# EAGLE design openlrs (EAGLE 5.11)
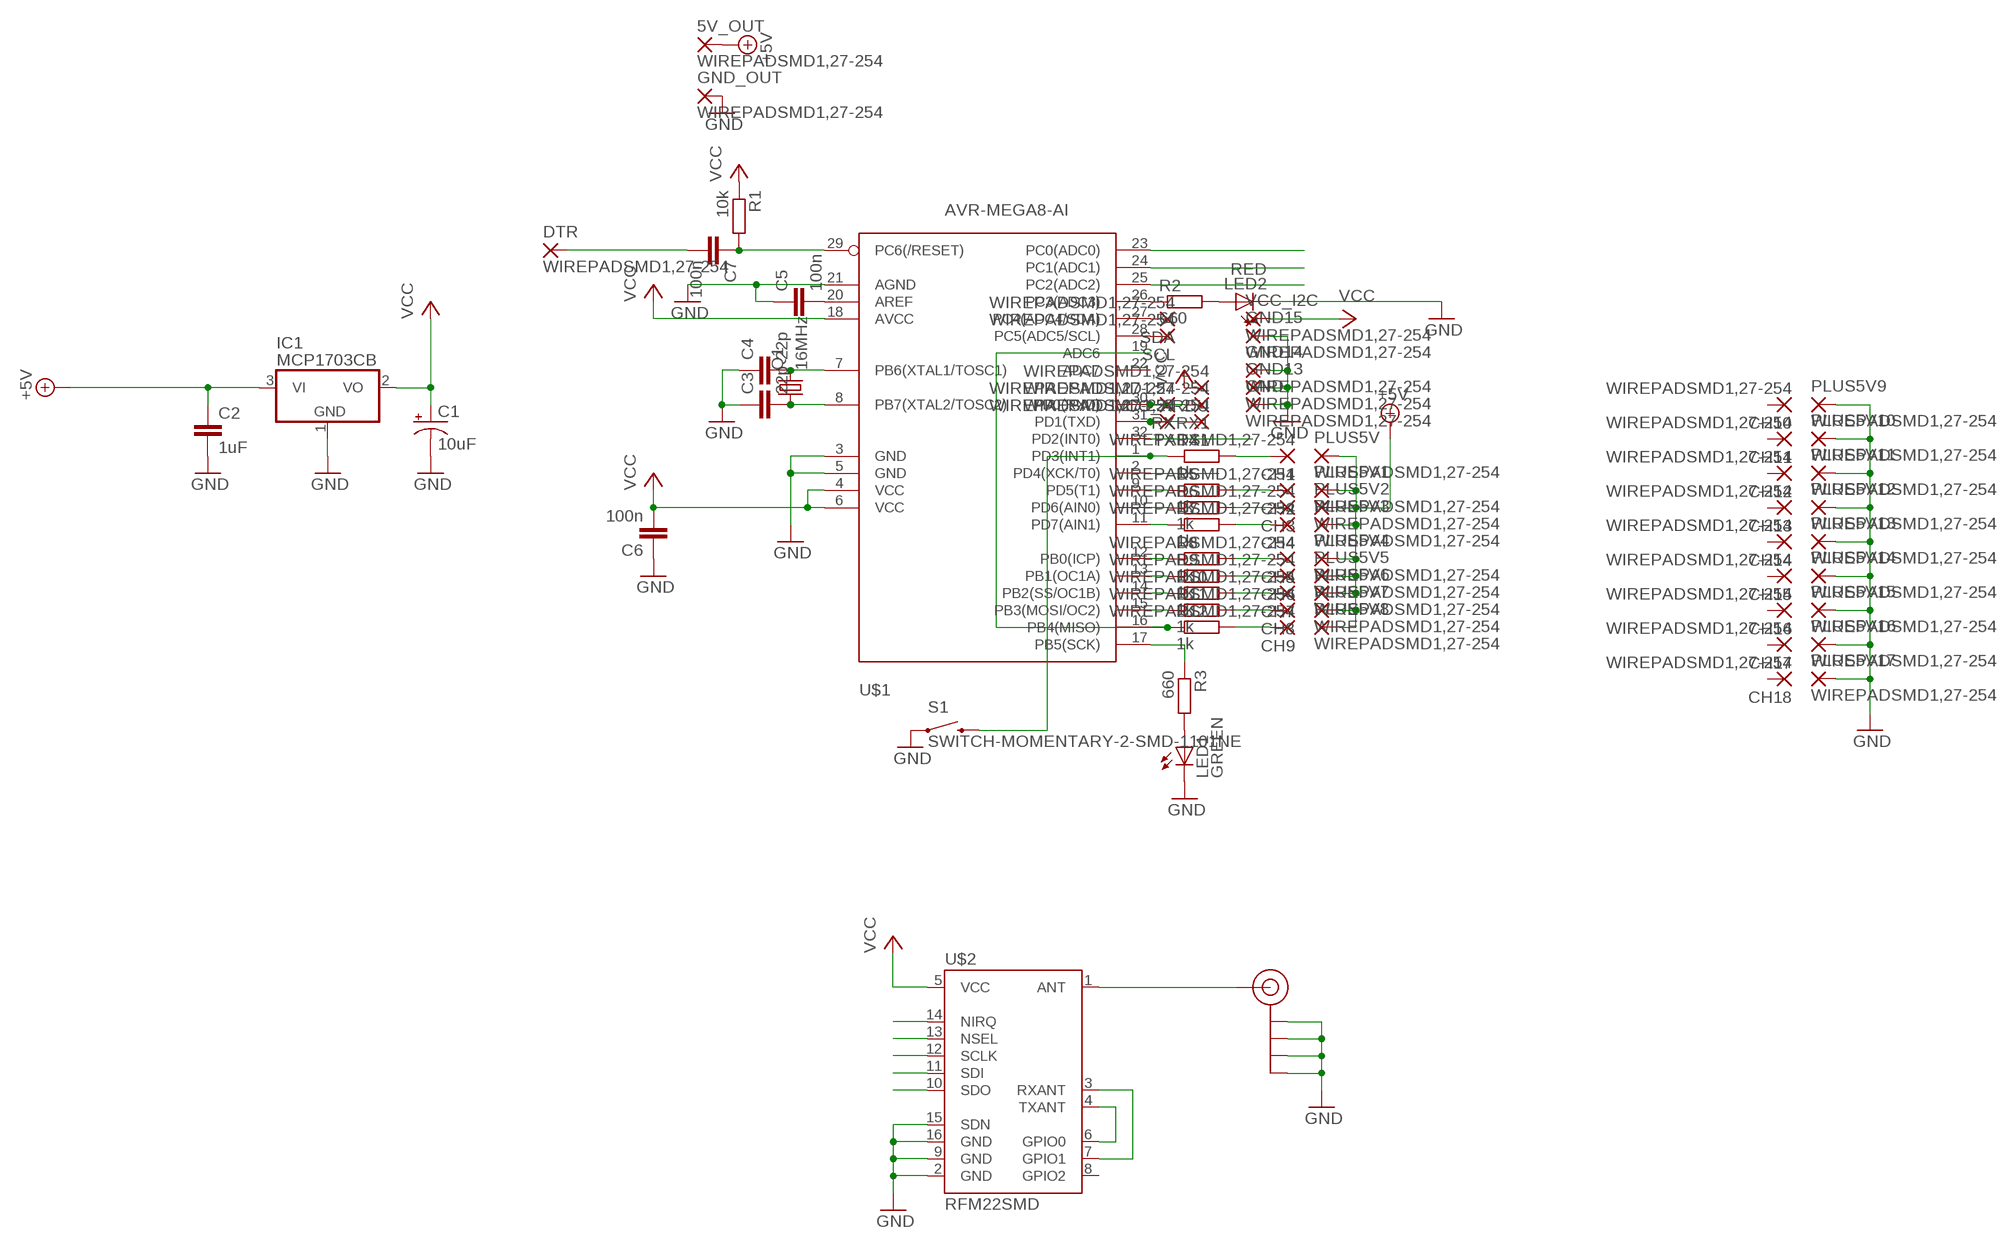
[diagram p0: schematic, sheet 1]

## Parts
5V_OUT  WIREPADSMD1,27-254  [SMD1,27-2,54]
C1  10uF  CAP_POL3528  [EIA3528]
C2  1uF  C-EUC0805K  [C0805K]
C3  22p  C-EUC0603K  [C0603K]
C4  22p  C-EUC0603K  [C0603K]
C5  100n  C-EUC0603K  [C0603K]
C6  100n  C-EUC0603K  [C0603K]
C7  100n  C-EUC0603K  [C0603K]
CH1  WIREPADSMD1,27-254  [SMD1,27-2,54]
CH2  WIREPADSMD1,27-254  [SMD1,27-2,54]
CH3  WIREPADSMD1,27-254  [SMD1,27-2,54]
CH4  WIREPADSMD1,27-254  [SMD1,27-2,54]
CH5  WIREPADSMD1,27-254  [SMD1,27-2,54]
CH6  WIREPADSMD1,27-254  [SMD1,27-2,54]
CH7  WIREPADSMD1,27-254  [SMD1,27-2,54]
CH8  WIREPADSMD1,27-254  [SMD1,27-2,54]
CH9  WIREPADSMD1,27-254  [SMD1,27-2,54]
CH10  WIREPADSMD1,27-254  [SMD1,27-2,54]
CH11  WIREPADSMD1,27-254  [SMD1,27-2,54]
CH12  WIREPADSMD1,27-254  [SMD1,27-2,54]
CH13  WIREPADSMD1,27-254  [SMD1,27-2,54]
CH14  WIREPADSMD1,27-254  [SMD1,27-2,54]
CH15  WIREPADSMD1,27-254  [SMD1,27-2,54]
CH16  WIREPADSMD1,27-254  [SMD1,27-2,54]
CH17  WIREPADSMD1,27-254  [SMD1,27-2,54]
CH18  WIREPADSMD1,27-254  [SMD1,27-2,54]
DTR  WIREPADSMD1,27-254  [SMD1,27-2,54]
GND  WIREPADSMD1,27-254  [SMD1,27-2,54]
GND13  WIREPADSMD1,27-254  [SMD1,27-2,54]
GND14  WIREPADSMD1,27-254  [SMD1,27-2,54]
GND15  WIREPADSMD1,27-254  [SMD1,27-2,54]
GND_OUT  WIREPADSMD1,27-254  [SMD1,27-2,54]
IC1  MCP1703CB  [SOT23]
J$1  SMA_EDGE  [SMA-EDGE]
LED1  GREEN  LEDCHIPLED_0603  [CHIPLED_0603]
LED2  RED  LEDCHIPLED_0603  [CHIPLED_0603]
PLUS5V  WIREPADSMD1,27-254  [SMD1,27-2,54]
PLUS5V1  WIREPADSMD1,27-254  [SMD1,27-2,54]
PLUS5V2  WIREPADSMD1,27-254  [SMD1,27-2,54]
PLUS5V3  WIREPADSMD1,27-254  [SMD1,27-2,54]
PLUS5V4  WIREPADSMD1,27-254  [SMD1,27-2,54]
PLUS5V5  WIREPADSMD1,27-254  [SMD1,27-2,54]
PLUS5V6  WIREPADSMD1,27-254  [SMD1,27-2,54]
PLUS5V7  WIREPADSMD1,27-254  [SMD1,27-2,54]
PLUS5V8  WIREPADSMD1,27-254  [SMD1,27-2,54]
PLUS5V9  WIREPADSMD1,27-254  [SMD1,27-2,54]
PLUS5V10  WIREPADSMD1,27-254  [SMD1,27-2,54]
PLUS5V11  WIREPADSMD1,27-254  [SMD1,27-2,54]
PLUS5V12  WIREPADSMD1,27-254  [SMD1,27-2,54]
PLUS5V13  WIREPADSMD1,27-254  [SMD1,27-2,54]
PLUS5V14  WIREPADSMD1,27-254  [SMD1,27-2,54]
PLUS5V15  WIREPADSMD1,27-254  [SMD1,27-2,54]
PLUS5V16  WIREPADSMD1,27-254  [SMD1,27-2,54]
PLUS5V17  WIREPADSMD1,27-254  [SMD1,27-2,54]
Q1  16MHz  CRYSTAL5X3  [CRYSTAL-SMD-5X3]
R1  10k  R-EU_R0603  [R0603]
R2  660  R-EU_R0603  [R0603]
R3  660  R-EU_R0603  [R0603]
R4  1k  R-EU_R0603  [R0603]
R5  1k  R-EU_R0603  [R0603]
R6  1k  R-EU_R0603  [R0603]
R7  1k  R-EU_R0603  [R0603]
R8  1k  R-EU_R0603  [R0603]
R9  1k  R-EU_R0603  [R0603]
R10  1k  R-EU_R0603  [R0603]
R11  1k  R-EU_R0603  [R0603]
R12  1k  R-EU_R0603  [R0603]
RX  WIREPADSMD1,27-254  [SMD1,27-2,54]
RX1  WIREPADSMD1,27-254  [SMD1,27-2,54]
S1  SWITCH-MOMENTARY-2-SMD-1101NE  [TACTILE-SWITCH-1101NE]
SCL  WIREPADSMD1,27-254  [SMD1,27-2,54]
SDA  WIREPADSMD1,27-254  [SMD1,27-2,54]
TX  WIREPADSMD1,27-254  [SMD1,27-2,54]
TX1  WIREPADSMD1,27-254  [SMD1,27-2,54]
U$1  AVR-MEGA8-AI  [TQFP32-08]
U$2  RFM22SMD  [RFM22-XXX-S2]
VCC_ARDU  WIREPADSMD1,27-254  [SMD1,27-2,54]
VCC_I2C  WIREPADSMD1,27-254  [SMD1,27-2,54]

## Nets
+5V: 5V_OUT.1(P) C2.1 IC1.3(VI) PLUS5V1.1(P) PLUS5V2.1(P) PLUS5V3.1(P) PLUS5V4.1(P) PLUS5V5.1(P) PLUS5V6.1(P) PLUS5V7.1(P) PLUS5V8.1(P) PLUS5V.1(P)
GND: C1.C(-) C2.2 C3.1 C4.1 C5.1 C6.1 GND13.1(P) GND14.1(P) GND15.1(P) GND.1(P) GND_OUT.1(P) IC1.1(GND) J$1.GND@0(GND) J$1.GND@1(GND) J$1.GND@2(GND) J$1.GND@3(GND) LED1.C LED2.C PLUS5V9.1(P) PLUS5V10.1(P) PLUS5V11.1(P) PLUS5V12.1(P) PLUS5V13.1(P) PLUS5V14.1(P) PLUS5V15.1(P) PLUS5V16.1(P) PLUS5V17.1(P) S1.P$1 U$1.3(GND) U$1.5(GND) U$1.21(AGND) U$2.2(GND) U$2.9(GND) U$2.15(SDN) U$2.16(GND)
INT0: U$1.32(PD2(INT0)) U$2.14(NIRQ)
N$1: C7.1 R1.2 U$1.29(PC6(/RESET))
N$2: C4.2 Q1.3 U$1.7(PB6(XTAL1/TOSC1))
N$3: C3.2 Q1.1 U$1.8(PB7(XTAL2/TOSC2))
N$4: C5.2 U$1.20(AREF)
N$5: R2.1 U$1.26(PC3(ADC3))
N$6: R3.1 U$1.17(PB5(SCK))
N$7: LED1.A R3.2
N$8: LED2.A R2.2
N$9: R12.1 U$1.16(PB4(MISO)) U$1.19(ADC6)
N$10: R4.1 S1.P$2 U$1.1(PD3(INT1))
N$11: CH1.1(P) R4.2
N$12: R5.1 U$1.9(PD5(T1))
N$13: CH2.1(P) R5.2
N$14: R6.1 U$1.10(PD6(AIN0))
N$15: CH3.1(P) R6.2
N$16: R7.1 U$1.11(PD7(AIN1))
N$17: CH4.1(P) R7.2
N$18: R8.1 U$1.12(PB0(ICP))
N$19: CH5.1(P) R8.2
N$20: R9.1 U$1.13(PB1(OC1A))
N$21: CH6.1(P) R9.2
N$22: R10.1 U$1.14(PB2(SS/OC1B))
N$23: CH7.1(P) R10.2
N$24: R11.1 U$1.15(PB3(MOSI/OC2))
N$25: CH8.1(P) R11.2
N$26: CH9.1(P) R12.2
N$27: J$1.SIG(SIGNAL) U$2.1(ANT)
N$28: U$2.4(TXANT) U$2.6(GPIO0)
N$29: U$2.3(RXANT) U$2.7(GPIO1)
N$30: RX1.1(P) RX.1(P) U$1.30(PD0(RXD))
N$31: TX1.1(P) TX.1(P) U$1.31(PD1(TXD))
N$32: C7.2 DTR.1(P)
N$33: SDA.1(P) U$1.27(PC4(ADC4/SDA))
N$35: SCL.1(P) U$1.28(PC5(ADC5/SCL))
SCK: U$1.25(PC2(ADC2)) U$2.12(SCLK)
SDI: U$1.24(PC1(ADC1)) U$2.11(SDI)
SDO: U$1.23(PC0(ADC0)) U$2.10(SDO)
VCC: C1.A(+) C6.2 IC1.2(VO) R1.1 U$1.4(VCC) U$1.6(VCC) U$1.18(AVCC) U$2.5(VCC) VCC_ARDU.1(P) VCC_I2C.1(P)
XCK: U$1.2(PD4(XCK/T0)) U$2.13(NSEL)
Unconnected: CH10.1(P) CH11.1(P) CH12.1(P) CH13.1(P) CH14.1(P) CH15.1(P) CH16.1(P) CH17.1(P) CH18.1(P) U$1.22(ADC7) U$2.8(GPIO2)

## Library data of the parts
5V_OUT CH1-CH18 DTR GND GND13-GND15 GND_OUT PLUS5V PLUS5V1-PLUS5V17 RX RX1 SCL SDA TX TX1 VCC_ARDU VCC_I2C = wirepad:WIREPAD: Wire PAD connect wire on PCB
C1 = SparkFun:CAP_POL: Capacitor Polarized
C2-C7 = resistor:C-EU: CAPACITOR, European symbol
IC1 = linear:MCP1703: 250 mA, 16V, Low Quiescent Current LDO Regulator Source: http://ww1.microchip.com/downloads/en/DeviceDoc/22049b.pdf
J$1 = SparkFun:SMA_EDGE: SMA Antenna Connector End launch SMA connector. The paste layer has been removed so that the connector can be hand soldered onto the board after reflow.
LED1 LED2 = led:LED: LED
Q1 = SparkFun:CRYSTAL: Crystals
R1-R12 = resistor:R-EU_: RESISTOR, European symbol
S1 = SparkFun:SWITCH-MOMENTARY-2
U$1 = SparkFun:AVR-MEGA8: MICROCONTROLLER 8 Kbytes FLASH 1 kbytes SRAM 512 bytes EEPROM USART 6-channel 10 bit ADC 2-channel 8 bit ADC
U$2 = SparkFun:RFM22: Description: The RFM22 is a low-power, low cost radio that is capable of operating in the 434MHz and 900MHz open bands. It's frequency is software defined and there are some very good libraries written for it.

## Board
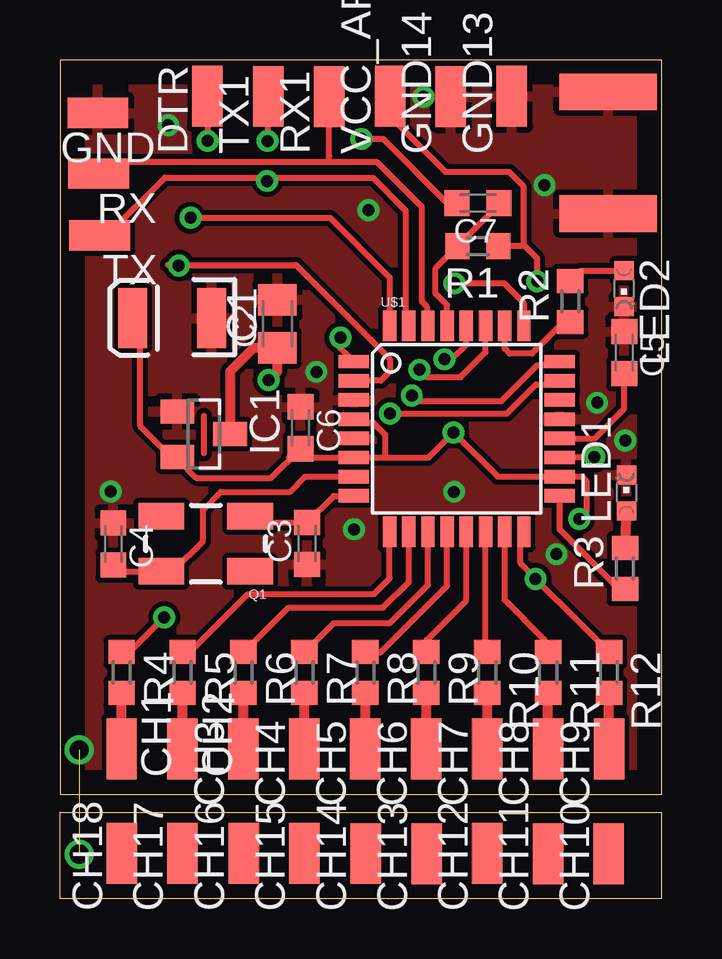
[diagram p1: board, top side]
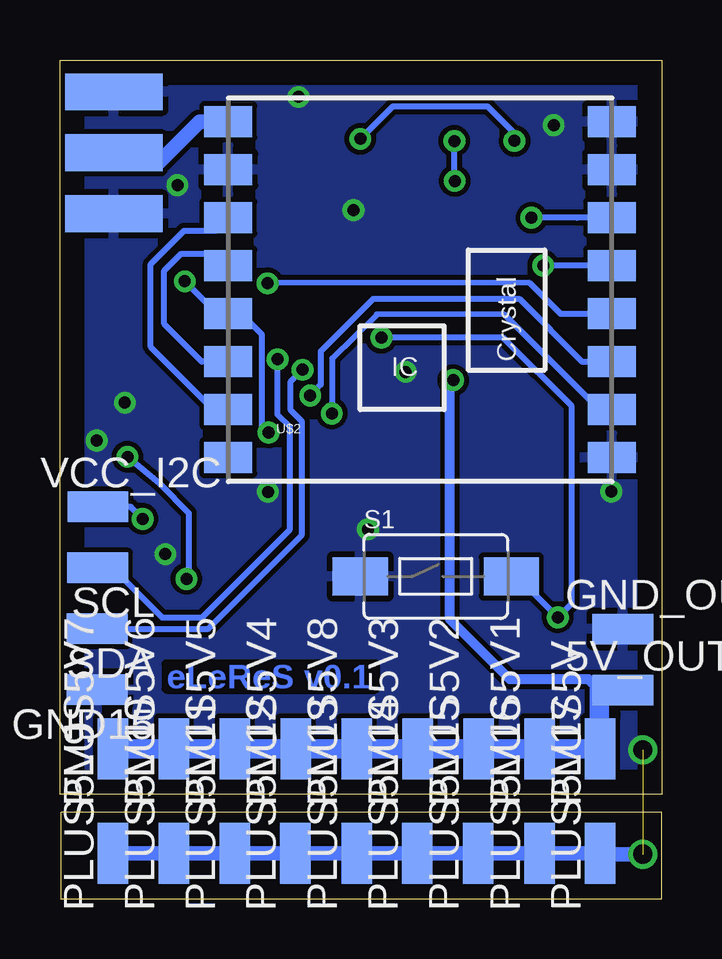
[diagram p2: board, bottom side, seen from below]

Size 25.1 x 34.96 mm. Coordinates in mm from the lower left corner, seen from the top.
Outline: 0.01,3.6 25.08,3.6 25.08,0 0.02,0 0.02,3.61
Outline: 0,4.34 25.1,4.34 25.1,34.96 0,34.96 0,4.34
Copper layers (1*16): Top 0.035mm / dielectric 1.5mm / Bottom 0.035mm
Design rules "default": minimum track width 10mil, minimum drill 24mil, track to track 8mil, track to pad 8mil, pad to pad 8mil, via to via 8mil, smd to smd 8mil, copper to edge 40mil, drill to drill 8mil, minimum pad ring 10mil, minimum via ring 8mil, stop-mask expansion 4mil, vias tented up to drill 0mil, thermal gap 10mil

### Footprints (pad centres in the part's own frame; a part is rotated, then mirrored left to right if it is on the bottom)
SMD1,27-2,54 = smd 1.27 x 2.54: 1 0,0
EIA3528 = smd 1.2 x 2.5: A 1.65,0; C -1.65,0
C0805K = smd 1.3 x 1.6: 1 -1,0; 2 1,0
C0603K = smd 1.05 x 1.08: 1 -0.875,0; 2 0.875,0
SOT23 = smd 1 x 1.4: 1 -0.95,-1.1; 2 0.95,-1.1; 3 0,1.1
SMA-EDGE = smd 1.524 x 4.064: GND@0 0,0; GND@1 5.08,0; SIG 2.54,0 | smd 1.524 x 4.064 bottom: GND@2 0,0; GND@3 5.08,0
CHIPLED_0603 = smd 0.8 x 0.8: A 0,-0.75; C 0,0.75
CRYSTAL-SMD-5X3 = smd 1.9 x 1.1: 1 -1.85,-1.15; 2 1.85,-1.15; 3 1.85,1.15; 4 -1.85,1.15
R0603 = smd 1 x 1.1: 1 -0.85,0; 2 0.85,0
TACTILE-SWITCH-1101NE = smd 2.3 x 1.6: P$1 -3.15,0; P$2 3.15,0
TQFP32-08 = smd 1.27 x 0.559: 1 -4.293,2.8; 2 -4.293,2; 3 -4.293,1.2; 4 -4.293,0.4; 5 -4.293,-0.4; 6 -4.293,-1.2; 7 -4.293,-2; 8 -4.293,-2.8; 17 4.293,-2.8; 18 4.293,-2; 19 4.293,-1.2; 20 4.293,-0.4; 21 4.293,0.4; 22 4.293,1.2; 23 4.293,2; 24 4.293,2.8 | smd 0.559 x 1.27: 9 -2.8,-4.293; 10 -2,-4.293; 11 -1.2,-4.293; 12 -0.4,-4.293; 13 0.4,-4.293; 14 1.2,-4.293; 15 2,-4.293; 16 2.8,-4.293; 25 2.8,4.293; 26 2,4.293; 27 1.2,4.293; 28 0.4,4.293; 29 -0.4,4.293; 30 -1.2,4.293; 31 -2,4.293; 32 -2.8,4.293
RFM22-XXX-S2 = smd 2 x 1.3: 1 -8,7; 2 -8,5; 3 -8,3; 4 -8,1; 5 -8,-1; 6 -8,-3; 7 -8,-5; 8 -8,-7; 9 8,-7; 10 8,-5; 11 8,-3; 12 8,-1; 13 8,1; 14 8,3; 15 8,5; 16 8,7

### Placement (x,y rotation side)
5V_OUT  1.63,8.69 270 bottom
C1  4.68,24.21 180 top
C2  9.07,23.96 90 top
C3  10.31,14.8 90 top
C4  2.23,14.79 270 top
C5  23.53,22.76 270 top
C6  10.04,19.62 270 top
C7  17.43,29 180 top
CH1  2.57,6.25 180 top
CH2  5.11,6.25 180 top
CH3  7.65,6.25 0 top
CH4  10.19,6.25 0 top
CH5  12.73,6.25 0 top
CH6  15.27,6.25 0 top
CH7  17.81,6.25 0 top
CH8  20.35,6.25 0 top
CH9  22.89,6.25 0 top
CH10  22.88,1.87 0 top
CH11  20.35,1.87 0 top
CH12  17.82,1.88 0 top
CH13  15.29,1.87 0 top
CH14  12.74,1.88 0 top
CH15  10.19,1.88 0 top
CH16  7.66,1.89 0 top
CH17  5.11,1.88 0 top
CH18  2.58,1.89 0 top
DTR  6.14,33.44 0 top
GND  1.58,32.75 90 top
GND13  18.84,33.44 0 top
GND14  16.29,33.44 0 top
GND15  23.56,8.71 90 bottom
GND_OUT  1.63,11.23 270 bottom
IC1  6,19.36 270 top
J$1  22.86,28.55 90 bottom
LED1  23.62,16.9 0 top
LED2  23.52,25.42 180 top
PLUS5V  2.57,6.25 0 bottom
PLUS5V1  5.11,6.25 0 bottom
PLUS5V2  7.65,6.25 0 bottom
PLUS5V3  10.19,6.25 0 bottom
PLUS5V4  15.27,6.25 0 bottom
PLUS5V5  17.81,6.25 0 bottom
PLUS5V6  20.35,6.25 0 bottom
PLUS5V7  22.89,6.25 0 bottom
PLUS5V8  12.73,6.25 0 bottom
PLUS5V9  22.89,1.88 0 bottom
PLUS5V10  20.35,1.88 0 bottom
PLUS5V11  17.81,1.88 0 bottom
PLUS5V12  15.29,1.88 0 bottom
PLUS5V13  12.73,1.88 0 bottom
PLUS5V14  10.2,1.88 0 bottom
PLUS5V15  7.66,1.89 0 bottom
PLUS5V16  5.1,1.88 0 bottom
PLUS5V17  2.58,1.89 0 bottom
Q1  6.08,14.79 180 top
R1  17.43,27.2 180 top
R2  21.27,24.89 90 top
R3  23.56,13.76 90 top
R4  2.57,9.42 270 top
R5  5.11,9.42 270 top
R6  7.65,9.42 270 top
R7  10.19,9.42 270 top
R8  12.73,9.42 270 top
R9  15.27,9.42 270 top
R10  17.81,9.42 270 top
R11  20.35,9.42 270 top
R12  22.89,9.42 270 top
RX  1.62,30.22 90 top
RX1  11.22,33.44 0 top
S1  9.44,13.43 0 bottom
SCL  23.53,13.79 90 bottom
SDA  23.55,11.25 90 bottom
TX  1.66,27.65 90 top
TX1  8.68,33.44 0 top
U$1  16.54,19.58 0 top
U$2  10.09,25.38 0 bottom
VCC_ARDU  13.77,33.44 0 top
VCC_I2C  23.52,16.33 270 bottom

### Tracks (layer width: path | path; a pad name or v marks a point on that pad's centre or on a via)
+5V  (via drill 0.5)
  Top 0.406: v8.7,21.61 9.07,21.98 C2.1 8.08,22.96 7.1,21.97 IC1.3
  Bottom 0.406: PLUS5V2.1 7.69,6.29 | 2.61,8.69 3.07,9.14 6.35,9.14 8.84,11.63 8.84,21.47 v8.7,21.61
  Bottom 0.61: 2.61,8.69 5V_OUT.1
  Bottom 0.813: PLUS5V.1 | PLUS5V.1 PLUS5V1.1 PLUS5V2.1 | 7.69,6.29 7.74,6.25 PLUS5V3.1 PLUS5V8.1 PLUS5V4.1 PLUS5V5.1 PLUS5V6.1 PLUS5V7.1 | PLUS5V.1 2.61,6.28 2.61,8.69
GND  (via drill 0.5, 0.8)  (1 unrouted)
  Bottom 0.61: v0.8,1.85 2.58,1.85 PLUS5V17.1 PLUS5V16.1 PLUS5V15.1 PLUS5V14.1 PLUS5V13.1 PLUS5V12.1 PLUS5V11.1 PLUS5V10.1 PLUS5V9.1
  other vias: 23.58,19.09 22.4,20.67 12.26,15.4 2.11,16.97 12.86,28.7 20.21,29.74 20.71,14.36 4.52,32.24 15.15,33.42 16.43,16.96 10.69,21.96 0.8,6.2
  pour Bottom: 0.79,34.9 25.26,34.9 25.09,4.38 -0.11,4.38 -0.19,34.26
  pour Top: 0.03,35.01 25.13,34.96 25.09,4.42 -0.01,4.47
INT0  (via drill 0.5)
  Top 0.254: U$1.32 13.74,25.89 11.25,28.38 v5.45,28.38
  Bottom 0.254: v5.45,28.38 3.54,28.38 U$2.14
N$1
  Top 0.254: U$1.29 16.14,24.74 15.66,25.22 15.66,26.28 R1.2 18.31,28.92 C7.1
N$2
  Top 0.254: Q1.3 2.7,13.64 C4.2 | U$1.7 10.21,17.58 9.58,16.96 6.71,16.96 5.96,16.21 5.96,14.89 4.75,13.68
  Top 0.406: Q1.3 4.75,13.68
N$3
  Top 0.254: Q1.1 8.63,15.67 C3.2 11.42,16.79 U$1.8
  Top 0.406: Q1.1 8.11,16.28
N$4
  Top 0.254: C5.2 23.53,20.42 22.3,19.18 U$1.20
N$5
  Top 0.254: U$1.26 18.54,22.92 18.75,22.72 19.68,22.72 20.74,23.77 21,23.77 R2.1
N$6
  Top 0.254: 21.14,16.77 20.85,16.77 U$1.17 20.84,15.38 23.31,12.91 R3.1
N$7
  Top 0.406: R3.2 23.59,14.95 LED1.A
N$8
  Top 0.254: R2.2 21.71,26.17 LED2.A
N$9  (via drill 0.5)
  Top 0.254: U$1.19 21.85,18.38 22.23,18.39 v22.29,18.41 | R12.1 21.66,11.51 v19.83,13.33 19.21,13.97 19.21,15.16 U$1.16
  Bottom 0.254: v22.29,18.41 20.95,17.31 19.72,16.06 19.72,13.44 v19.83,13.33
N$10  (via drill 0.5)
  Top 0.254: U$1.1 11.7,22.94 v11.7,23.38 | R4.1 2.91,10.27 v4.35,11.72
  Bottom 0.254: v11.7,23.38 v11.69,23.39 6.62,23.38 6.52,23.28 3.76,20.53 3.76,12.31 v4.35,11.72 6.05,13.43 S1.P$2
N$11
  Top 0.406: CH1.1 R4.2
N$12
  Top 0.254: U$1.9 13.74,13.35 13.1,12.7 7.85,12.69 6.51,11.36 5.54,10.39 R5.1
  Top 0.406: U$1.9
N$13
  Top 0.406: CH2.1 R5.2
N$14
  Top 0.254: U$1.10 14.54,13.2 13.47,12.13 9.54,12.13 7.68,10.27 R6.1 7.65,10.3
N$15
  Top 0.406: CH3.1 R6.2
N$16
  Top 0.254: U$1.11 15.34,13.08 13.75,11.49 11.43,11.49 10.21,10.27 R7.1
N$17
  Top 0.406: CH4.1 R7.2
N$18
  Top 0.254: U$1.12 16.14,13.04 13.36,10.26 R8.1
N$19
  Top 0.406: CH5.1 R8.2
N$20
  Top 0.254: U$1.13 16.94,12.43 15.3,10.79 15.3,10.3 R9.1
N$21
  Top 0.406: CH6.1 R9.2
N$22
  Top 0.254: U$1.14 17.74,10.34 R10.1
N$23
  Top 0.406: CH7.1 R10.2
N$24
  Top 0.254: U$1.15 18.54,12.45 20.19,10.8 20.19,10.44 R11.1
N$25
  Top 0.406: CH8.1 R11.2
N$26
  Top 0.406: CH9.1 R12.2
N$27
  Bottom 0.61: U$2.1 19.29,32.38 20.98,30.7 22.78,30.7 J$1.SIG
N$28
  Bottom 0.254: U$2.4 17.81,25.93 18.76,26.88 20.05,26.88 20.09,26.85 20.76,26.18 20.76,23.95 19.19,22.38 U$2.6
N$29
  Bottom 0.254: U$2.3 18.63,27.84 19.93,27.84 21.32,26.45 21.32,23 18.72,20.39 U$2.7
N$30
  Top 0.254: RX.1 2.71,30.23 2.82,30.72 11.22,30.72 | 11.22,30.72 13.21,30.72 15.07,28.85 15.07,24.91 15.3,24.68 15.31,23.91 U$1.30 | RX1.1 11.22,30.98 11.22,30.72
N$31  (via drill 0.5)
  Top 0.254: U$1.31 14.41,24.02 14.41,28.68 13.04,30.05 8.65,30.05 | TX.1 2.02,27.71 4.38,30.05 8.65,30.05 | TX1.1 8.68,31.78 v8.66,31.58 | 8.65,30.05 v8.64,29.91
  Bottom 0.254: v8.66,31.58 8.65,29.99 v8.64,29.91
N$32  (via drill 0.5)
  Top 0.254: v6.15,31.59 6.15,33.43 DTR.1 | C7.2 16.14,29 13.47,31.67 v12.58,31.67
  Bottom 0.254: v6.15,31.59 6.15,31.9 7.27,33.01 11.24,33.01 v12.58,31.67
N$33  (via drill 0.5)
  Top 0.254: U$1.27 17.74,22.77 16.7,21.73 15.3,21.73 v14.99,22.05
  Bottom 0.254: v14.99,22.05 15.49,21.55 15.49,20.36 15.02,19.89 15.02,15.16 18.95,11.22 22.26,11.22 22.29,11.25 SDA.1
N$34
  Top 0.254: 5.99,20.12 6.01,20.12 6.01,18.56
N$35  (via drill 0.5)
  Top 0.254: U$1.28 16.94,23.08 16.33,22.47 16.05,22.47 v16.03,22.48
  Bottom 0.254: v16.03,22.48 16.03,20.19 15.52,19.67 15.52,15.39 19.2,11.71 20.82,11.71 22.88,13.77 SCL.1
SCK  (via drill 0.5)
  Top 0.254: U$1.25 19.34,24.82 18.51,25.65 v16.44,25.65
  Bottom 0.254: v16.44,25.65 5.53,25.68 4.22,24.37 2.11,24.37 U$2.12
SDI  (via drill 0.5)
  Top 0.254: U$1.24 20.36,22.38 20.2,22.24 19.91,22.24 18.4,20.74 14.91,20.73 v14.67,20.97
  Bottom 0.254: U$2.11 2.11,22.37 3.31,22.37 5.95,25 12.05,25 14.24,22.81 14.24,22.7 14.23,21.43 14.58,21.05 v14.67,20.97
SDO  (via drill 0.5)
  Top 0.254: v13.77,20.22 14.91,20.21 18.63,20.21 18.87,20.45 19.85,21.44 20.24,21.44 20.39,21.58 U$1.23
  Bottom 0.254: v13.77,20.22 13.75,22.51 11.89,24.35 6.59,24.36 2.64,20.4 U$2.10
VCC  (via drill 0.5)
  Top 0.254: U$1.6 12.29,18.35 | U$1.4 12.7,19.98 12.86,19.83 13.06,19.83 13.57,19.32 13.57,18.43 13.52,18.38 | U$1.6 9.53,18.38 C6.2 8.8,17.54 5.69,17.54 4.9,18.33 IC1.2 4.64,18.41 3.35,19.71 3.35,24.14 C1.A | v19.9,25.74 19.9,26.69 19.39,27.19 | 19.39,27.19 R1.1 | VCC_ARDU.1 13.77,32.61 16.09,30.29 18.74,30.29 19.34,29.69 19.34,27.24 19.39,27.19 | U$1.6 13.52,18.38 | 13.52,18.38 15.36,18.38 v16.4,19.43 | v16.4,19.43 18.25,17.58 U$1.18 21.75,17.58 21.94,17.4 21.94,16.11 v21.66,15.83 | v16.4,19.43 v16.41,19.44
  Bottom 0.254: v19.9,25.74 18.55,24.38 U$2.5 17.55,24.38 16.69,23.52 16.69,19.71 v16.4,19.43 | v21.66,15.83 22.15,16.33 VCC_I2C.1
XCK  (via drill 0.5)
  Top 0.254: U$1.2 13.38,21.58 13.76,21.96 13.76,22.49 9.84,26.41 4.5,26.41 v4.95,26.39
  Bottom 0.254: v4.95,26.39 U$2.13

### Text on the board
Bottom: eLeReS v0.1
